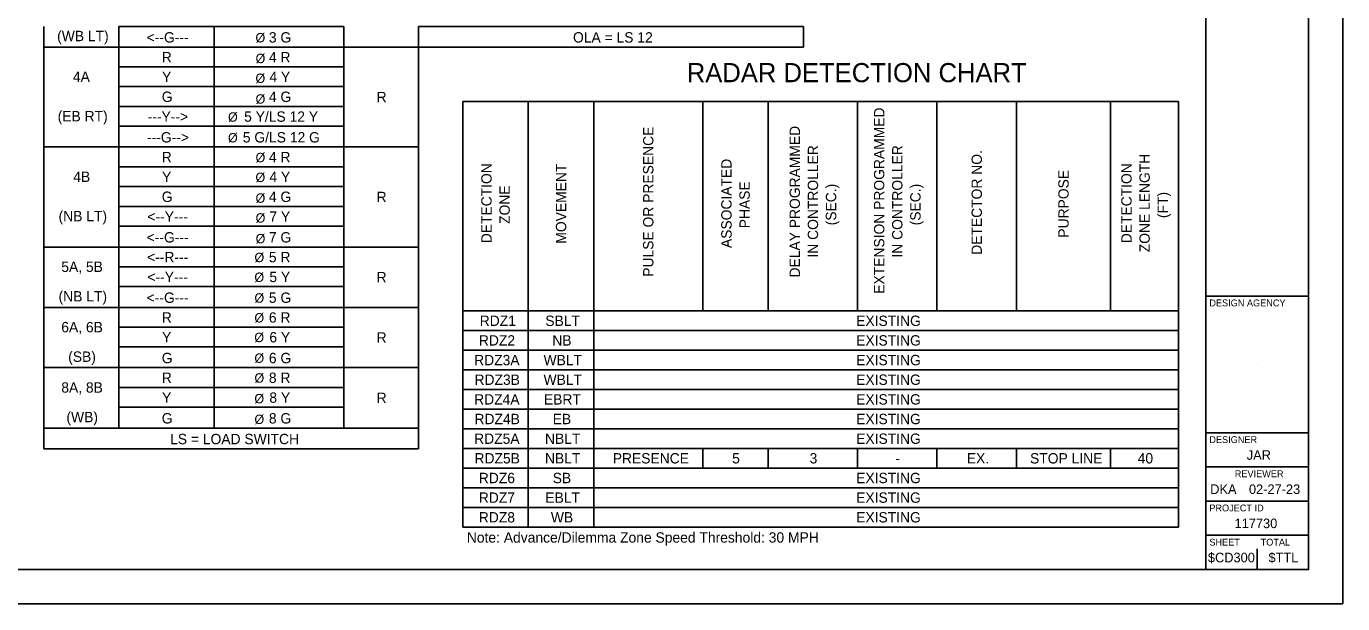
# Model space of a CAD drawing. Extents: x 0 to 34, y 0 to 22.
# Drawn here: x 14.75 to 34, y 0 to 8.45 of the extents above; entities that cross this region are included whole.
import ezdxf

# ---------------------------------------------------------------- set-up
doc = ezdxf.new("R2010")
doc.units = 0
for name, color, linetype in [('SG_P_Text', 7, 'Continuous'), ('SH_Border', 7, 'Continuous'), ('SH_Cut_Line', 7, 'Continuous'), ('SH_Data', 7, 'Continuous'), ('SH_Text', 7, 'Continuous')]:
    doc.layers.add(name, color=color, linetype=linetype)

msp = doc.modelspace()

# ---------------------------------------------------------------- linework, layer by layer
at = {"layer": 'SH_Border'}
for p, q in [((32, 0.5), (32, 21.5)), ((32, 4.5), (33.5, 4.5)), ((32, 2.5), (33.5, 2.5)), ((32, 2), (33.5, 2)), ((32, 1.5), (33.5, 1.5)), ((32, 1), (33.5, 1))]:
    msp.add_line(p, q, dxfattribs=at)
msp.add_lwpolyline([(1.5, 21.5), (33.5, 21.5), (33.5, 0.5), (1.5, 0.5)], close=True, dxfattribs=at)
at = {"layer": 'SH_Cut_Line'}
msp.add_lwpolyline([(0, 0), (34, 0), (34, 22), (0, 22)], close=True, dxfattribs=at)
at = {"layer": 'SH_Data'}
for p, q in [((32.75, 3.5), (32.75, 3.5)), ((32.75, 0.5), (32.75, 0.8)), ((32.375, 0.675), (32.375, 0.675))]:
    msp.add_line(p, q, dxfattribs=at)
at = {"layer": 'SH_Text'}
for p, q in [((15.005, 8.446), (15.005, 8.143)), ((16.099, 8.446), (19.393, 8.446)), ((16.099, 8.446), (16.099, 8.143)), ((17.495, 8.446), (17.495, 8.143)), ((19.393, 8.446), (19.393, 8.143)), ((20.486, 8.446), (26.113, 8.446)), ((20.486, 8.446), (20.486, 8.143)), ((26.113, 8.446), (26.113, 8.143)), ((15.005, 8.143), (20.486, 8.143)), ((15.005, 8.143), (15.005, 7.854)), ((16.099, 8.143), (16.099, 7.854)), ((17.495, 8.143), (17.495, 7.854)), ((19.393, 8.143), (19.393, 7.854)), ((20.486, 8.143), (26.113, 8.143)), ((20.486, 8.143), (20.486, 7.854)), ((15.005, 7.854), (15.005, 7.274)), ((16.099, 7.854), (19.393, 7.854)), ((16.099, 7.854), (16.099, 7.274)), ((17.495, 7.854), (17.495, 7.274)), ((19.393, 7.854), (19.393, 7.274)), ((20.486, 7.854), (20.486, 7.274)), ((16.099, 7.564), (19.393, 7.564)), ((21.131, 7.349), (26.905, 7.349)), ((21.131, 7.349), (21.131, 3.42)), ((22.09, 7.349), (22.09, 3.42)), ((23.048, 7.349), (23.048, 3.42)), ((24.641, 7.349), (24.641, 4.283)), ((25.599, 7.349), (25.599, 4.283)), ((26.905, 7.349), (29.229, 7.349)), ((26.905, 7.349), (26.905, 4.283)), ((28.067, 7.349), (28.067, 4.283)), ((29.229, 7.349), (31.601, 7.349)), ((29.229, 7.349), (29.229, 4.283)), ((30.606, 7.349), (30.606, 4.283)), ((31.601, 7.349), (31.601, 3.42)), ((15.005, 7.274), (15.005, 5.521)), ((16.099, 7.274), (19.393, 7.274)), ((16.099, 7.274), (16.099, 5.521)), ((17.495, 7.274), (17.495, 5.521)), ((19.393, 7.274), (19.393, 5.521)), ((20.486, 7.274), (20.486, 5.521)), ((16.099, 6.984), (19.393, 6.984)), ((15.005, 6.681), (20.486, 6.681)), ((16.099, 6.391), (19.393, 6.391)), ((16.099, 6.101), (19.393, 6.101)), ((16.099, 5.811), (19.393, 5.811)), ((15.005, 5.521), (15.005, 5.218)), ((16.099, 5.521), (19.393, 5.521)), ((16.099, 5.521), (16.099, 5.218)), ((17.495, 5.521), (17.495, 5.218)), ((19.393, 5.521), (19.393, 5.218)), ((20.486, 5.521), (20.486, 5.218)), ((15.005, 5.218), (20.486, 5.218)), ((15.005, 5.218), (15.005, 4.928)), ((16.099, 5.218), (16.099, 4.928)), ((17.495, 5.218), (17.495, 4.928)), ((19.393, 5.218), (19.393, 4.928)), ((20.486, 5.218), (20.486, 4.928)), ((15.005, 4.928), (15.005, 2.267)), ((16.099, 4.928), (19.393, 4.928)), ((16.099, 4.928), (16.099, 2.57)), ((17.495, 4.928), (17.495, 2.57)), ((19.393, 4.928), (19.393, 2.57)), ((20.486, 4.928), (20.486, 2.267)), ((16.099, 4.638), (19.393, 4.638)), ((15.005, 4.335), (20.486, 4.335)), ((21.131, 4.283), (26.905, 4.283)), ((26.905, 4.283), (29.229, 4.283)), ((29.229, 4.283), (31.601, 4.283)), ((16.099, 4.046), (19.393, 4.046)), ((21.131, 3.995), (26.905, 3.995)), ((26.905, 3.995), (29.229, 3.995)), ((29.229, 3.995), (31.601, 3.995)), ((16.099, 3.756), (19.393, 3.756)), ((21.131, 3.708), (26.905, 3.708)), ((26.905, 3.708), (29.229, 3.708)), ((29.229, 3.708), (31.601, 3.708)), ((15.005, 3.453), (20.486, 3.453)), ((21.131, 3.42), (26.905, 3.42)), ((21.131, 3.42), (21.131, 2.558)), ((22.09, 3.42), (22.09, 2.558)), ((23.048, 3.42), (23.048, 2.558)), ((26.905, 3.42), (29.229, 3.42)), ((29.229, 3.42), (31.601, 3.42)), ((31.601, 3.42), (31.601, 2.558)), ((16.099, 3.163), (19.393, 3.163)), ((21.131, 3.133), (26.905, 3.133)), ((26.905, 3.133), (29.229, 3.133)), ((29.229, 3.133), (31.601, 3.133)), ((16.099, 2.873), (19.393, 2.873)), ((21.131, 2.845), (26.905, 2.845)), ((26.905, 2.845), (29.229, 2.845)), ((29.229, 2.845), (31.601, 2.845)), ((15.005, 2.57), (20.486, 2.57)), ((21.131, 2.558), (26.905, 2.558)), ((21.131, 2.558), (21.131, 2.27)), ((22.09, 2.558), (22.09, 2.27)), ((23.048, 2.558), (23.048, 2.27)), ((26.905, 2.558), (29.229, 2.558)), ((29.229, 2.558), (31.601, 2.558)), ((31.601, 2.558), (31.601, 2.27)), ((15.005, 2.267), (20.486, 2.267)), ((21.131, 2.27), (26.905, 2.27)), ((21.131, 2.27), (21.131, 1.695)), ((22.09, 2.27), (22.09, 1.695)), ((23.048, 2.27), (23.048, 1.695)), ((24.641, 2.27), (24.641, 1.983)), ((25.599, 2.27), (25.599, 1.983)), ((26.905, 2.27), (29.229, 2.27)), ((26.905, 2.27), (26.905, 1.983)), ((28.067, 2.27), (28.067, 1.983)), ((29.229, 2.27), (31.601, 2.27)), ((29.229, 2.27), (29.229, 1.983)), ((30.606, 2.27), (30.606, 1.983)), ((31.601, 2.27), (31.601, 1.695)), ((21.131, 1.983), (26.905, 1.983)), ((26.905, 1.983), (29.229, 1.983)), ((29.229, 1.983), (31.601, 1.983)), ((21.131, 1.695), (26.905, 1.695)), ((21.131, 1.695), (21.131, 1.408)), ((22.09, 1.695), (22.09, 1.408)), ((23.048, 1.695), (23.048, 1.408)), ((26.905, 1.695), (29.229, 1.695)), ((29.229, 1.695), (31.601, 1.695)), ((31.601, 1.695), (31.601, 1.408)), ((21.131, 1.408), (26.905, 1.408)), ((21.131, 1.408), (21.131, 1.12)), ((22.09, 1.408), (22.09, 1.12)), ((23.048, 1.408), (23.048, 1.12)), ((26.905, 1.408), (29.229, 1.408)), ((29.229, 1.408), (31.601, 1.408)), ((31.601, 1.408), (31.601, 1.12)), ((21.131, 1.12), (26.905, 1.12)), ((26.905, 1.12), (29.229, 1.12)), ((29.229, 1.12), (31.601, 1.12))]:
    msp.add_line(p, q, dxfattribs=at)

# ---------------------------------------------------------------- texts
at = {"layer": 'SG_P_Text'}
msp.add_text('RADAR DETECTION CHART', height=0.28, dxfattribs=at).set_placement((24.407, 7.629))
at = {"layer": 'SH_Data'}
for s, height, p in [('DESIGN AGENCY', 0.1, (32.05, 4.35)), ('DESIGNER', 0.1, (32.05, 2.35)), ('JAR', 0.14, (32.597, 2.105)), ('REVIEWER', 0.1, (32.422, 1.85)), ('DKA', 0.14, (32.063, 1.605)), ('02-27-23', 0.14, (32.629, 1.605)), ('PROJECT ID', 0.1, (32.05, 1.35)), ('117730', 0.14, (32.419, 1.105)), ('SHEET', 0.1, (32.05, 0.85)), ('TOTAL', 0.1, (32.8, 0.85)), ('$CD300', 0.14, (32.029, 0.605)), ('$TTL', 0.14, (32.915, 0.605))]:
    msp.add_text(s, height=height, dxfattribs=at).set_placement(p)
at = {"layer": 'SH_Text'}
for s, height, p in [('(WB LT)', 0.1515, (15.199, 8.229)), ('<--G---', 0.1515, (16.509, 8.209)), ('Ø', 0.137, (18.1, 8.211)), ('3 G', 0.1515, (18.296, 8.209)), ('OLA = LS 12', 0.15153, (22.744, 8.209)), ('R', 0.152, (16.729, 7.919)), ('Ø', 0.137, (18.101, 7.908)), ('4 R', 0.1515, (18.296, 7.919)), ('4A', 0.1515, (15.43, 7.633)), ('Y', 0.152, (16.733, 7.63)), ('Ø', 0.137, (18.1, 7.618)), ('4 Y', 0.1515, (18.303, 7.63)), ('G', 0.152, (16.729, 7.34)), ('Ø', 0.137, (18.101, 7.315)), ('4 G', 0.1515, (18.296, 7.34)), ('R', 0.152, (19.871, 7.336)), ('(EB RT)', 0.1515, (15.207, 7.056)), ('---Y-->', 0.1515, (16.524, 7.05)), ('Ø', 0.137, (17.698, 7.051)), ('5 Y/LS 12 Y', 0.15153, (17.934, 7.05)), ('---G-->', 0.1515, (16.513, 6.747)), ('Ø', 0.137, (17.698, 6.748)), ('5 G/LS 12 G', 0.15153, (17.915, 6.747)), ('R', 0.152, (16.729, 6.457)), ('Ø', 0.137, (18.101, 6.458)), ('4 R', 0.1515, (18.296, 6.457)), ('4B', 0.1515, (15.435, 6.17)), ('Y', 0.152, (16.733, 6.167)), ('Ø', 0.137, (18.1, 6.168)), ('4 Y', 0.1515, (18.303, 6.167)), ('G', 0.152, (16.729, 5.877)), ('Ø', 0.137, (18.101, 5.865)), ('4 G', 0.1515, (18.296, 5.877)), ('R', 0.152, (19.871, 5.874)), ('(NB LT)', 0.1515, (15.22, 5.594)), ('<--Y---', 0.1515, (16.52, 5.587)), ('Ø', 0.137, (18.102, 5.575)), ('7 Y', 0.1515, (18.303, 5.587)), ('<--G---', 0.1515, (16.509, 5.284)), ('Ø', 0.137, (18.102, 5.272)), ('7 G', 0.1515, (18.296, 5.284)), ('<--R---', 0.1515, (16.515, 4.994)), ('Ø', 0.137, (18.085, 4.997)), ('5 R', 0.1515, (18.296, 4.994)), ('5A, 5B', 0.1515, (15.26, 4.853)), ('<--Y---', 0.1515, (16.52, 4.704)), ('Ø', 0.137, (18.084, 4.707)), ('5 Y', 0.1515, (18.303, 4.704)), ('R', 0.152, (19.871, 4.701)), ('(NB LT)', 0.1515, (15.22, 4.421)), ('<--G---', 0.1515, (16.509, 4.401)), ('Ø', 0.137, (18.085, 4.404)), ('5 G', 0.1515, (18.296, 4.401)), ('R', 0.152, (16.729, 4.111)), ('Ø', 0.137, (18.084, 4.114)), ('6 R', 0.1515, (18.296, 4.111)), ('6A, 6B', 0.1515, (15.26, 3.97)), ('RDZ1', 0.1515, (21.379, 4.063)), ('SBLT', 0.1515, (22.339, 4.063)), ('EXISTING', 0.1515, (26.885, 4.063)), ('Y', 0.152, (16.733, 3.822)), ('Ø', 0.137, (18.083, 3.827)), ('6 Y', 0.1515, (18.303, 3.822)), ('R', 0.152, (19.871, 3.818)), ('RDZ2', 0.1515, (21.367, 3.776)), ('NB', 0.1515, (22.441, 3.776)), ('EXISTING', 0.1515, (26.885, 3.776)), ('(SB)', 0.1515, (15.361, 3.538)), ('G', 0.152, (16.729, 3.518)), ('Ø', 0.137, (18.084, 3.524)), ('6 G', 0.1515, (18.296, 3.518)), ('RDZ3A', 0.1515, (21.298, 3.488)), ('WBLT', 0.1515, (22.313, 3.488)), ('EXISTING', 0.1515, (26.885, 3.488)), ('R', 0.152, (16.729, 3.229)), ('Ø', 0.137, (18.085, 3.234)), ('8 R', 0.1515, (18.296, 3.229)), ('RDZ3B', 0.1515, (21.303, 3.201)), ('WBLT', 0.1515, (22.313, 3.201)), ('EXISTING', 0.1515, (26.885, 3.201)), ('8A, 8B', 0.1515, (15.26, 3.087)), ('Y', 0.152, (16.733, 2.939)), ('8 Y', 0.1515, (18.303, 2.939)), ('R', 0.152, (19.871, 2.935)), ('Ø', 0.137, (18.084, 2.931)), ('RDZ4A', 0.1515, (21.298, 2.913)), ('EBRT', 0.1515, (22.318, 2.913)), ('EXISTING', 0.1515, (26.885, 2.913)), ('(WB)', 0.1515, (15.335, 2.655)), ('G', 0.152, (16.729, 2.636)), ('Ø', 0.137, (18.085, 2.628)), ('8 G', 0.1515, (18.296, 2.636)), ('RDZ4B', 0.1515, (21.303, 2.626)), ('EB', 0.1515, (22.447, 2.626)), ('EXISTING', 0.1515, (26.885, 2.626)), ('LS = LOAD SWITCH', 0.15153, (16.851, 2.333)), ('RDZ5A', 0.1515, (21.298, 2.338)), ('NBLT', 0.1515, (22.334, 2.338)), ('EXISTING', 0.1515, (26.885, 2.338)), ('RDZ5B', 0.1515, (21.303, 2.051)), ('NBLT', 0.1515, (22.334, 2.051)), ('PRESENCE', 0.1515, (23.325, 2.051)), ('5', 0.152, (25.071, 2.051)), ('3', 0.152, (26.204, 2.051)), ('-', 0.152, (27.457, 2.051)), ('EX.', 0.1515, (28.503, 2.051)), ('STOP LINE', 0.1515, (29.428, 2.051)), ('40', 0.1515, (31.002, 2.051)), ('RDZ6', 0.1515, (21.366, 1.763)), ('SB', 0.1515, (22.447, 1.763)), ('EXISTING', 0.1515, (26.885, 1.763)), ('RDZ7', 0.1515, (21.366, 1.476)), ('EBLT', 0.1515, (22.339, 1.476)), ('EXISTING', 0.1515, (26.885, 1.476)), ('RDZ8', 0.1515, (21.366, 1.188)), ('WB', 0.1515, (22.42, 1.188)), ('EXISTING', 0.1515, (26.885, 1.188)), ('Note: Advance/Dilemma Zone Speed Threshold: 30 MPH', 0.15153, (21.191, 0.893))]:
    msp.add_text(s, height=height, dxfattribs=at).set_placement(p)
for s, height, p in [('EXTENSION PROGRAMMED', 0.15153, (27.297, 4.534)), ('PULSE OR PRESENCE', 0.15153, (23.92, 4.783)), ('DELAY PROGRAMMED', 0.15153, (26.063, 4.772)), (' IN CONTROLLER', 0.15153, (26.328, 5.007)), (' IN CONTROLLER', 0.15153, (27.562, 5.007)), ('DETECTOR NO.', 0.15153, (28.724, 5.104)), ('ZONE LENGTH', 0.15153, (31.179, 5.141)), ('DETECTION', 0.1515, (21.554, 5.273)), ('MOVEMENT', 0.1515, (22.645, 5.267)), ('ASSOCIATED', 0.1515, (25.063, 5.203)), ('DETECTION', 0.1515, (30.914, 5.273)), ('PHASE', 0.1515, (25.329, 5.492)), ('PURPOSE', 0.1515, (29.993, 5.355)), ('ZONE', 0.1515, (21.819, 5.556)), ('(SEC.)', 0.1515, (26.593, 5.535)), ('(SEC.)', 0.1515, (27.827, 5.535)), ('(FT)', 0.1515, (31.444, 5.641))]:
    msp.add_text(s, height=height, rotation=90, dxfattribs=at).set_placement(p)

doc.saveas('drawing.dxf')
